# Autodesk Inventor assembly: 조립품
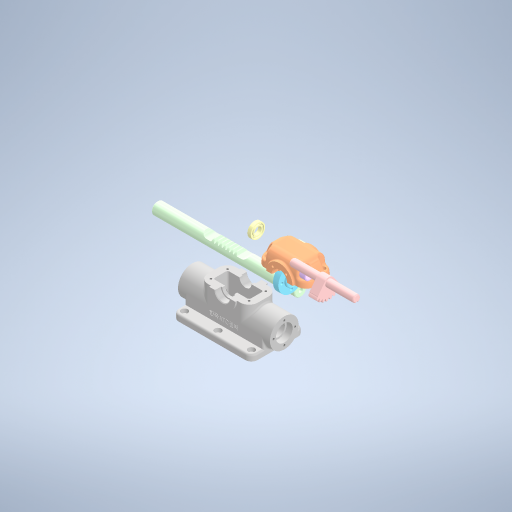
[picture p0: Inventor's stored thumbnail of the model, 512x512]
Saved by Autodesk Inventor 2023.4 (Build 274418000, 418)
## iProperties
Created: 2024-06
Part Number: 조립품
Document SubType Name: Assembly
Designer: edu-40
Author: edu-40
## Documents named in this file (13)
- C:\Users\edu-40\Desktop\740604V1003\조립품.iam
- C:\Users\edu-40\Desktop\740604V1003\본체.ipt
- C:\Users\edu-40\Desktop\740604V1003\깊은 홈 볼 베어링 6901\깊은 홈 볼 베어링 6901.ipt
- C:\Users\edu-40\Desktop\740604V1003\랙\랙.ipt
- C:\Users\edu-40\Desktop\740604V1003\베어링 커버\베어링 커버.ipt
- C:\Users\edu-40\Desktop\740604V1003\부시 커버\부시 커버.ipt
- C:\Users\edu-40\Desktop\740604V1003\스프링 와셔 M4\스프링 와셔 M4.ipt
- C:\Users\edu-40\Desktop\740604V1003\오일레스 부시\오일레스 부시.ipt
- C:\Users\edu-40\Desktop\740604V1003\오일실 12 22 7\오일실 12 22 7.ipt
- C:\Users\edu-40\Desktop\740604V1003\윗커버\윗커버.ipt
- C:\Users\edu-40\Desktop\740604V1003\육각 소켓 머리 볼트 M4x10\육각 소켓 머리 볼트 M4x10.ipt
- C:\Users\edu-40\Desktop\740604V1003\칼라\칼라.ipt
- C:\Users\edu-40\Desktop\740604V1003\피니언\피니언.ipt
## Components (1 placed, 1 different names)
1. 피니언:1
